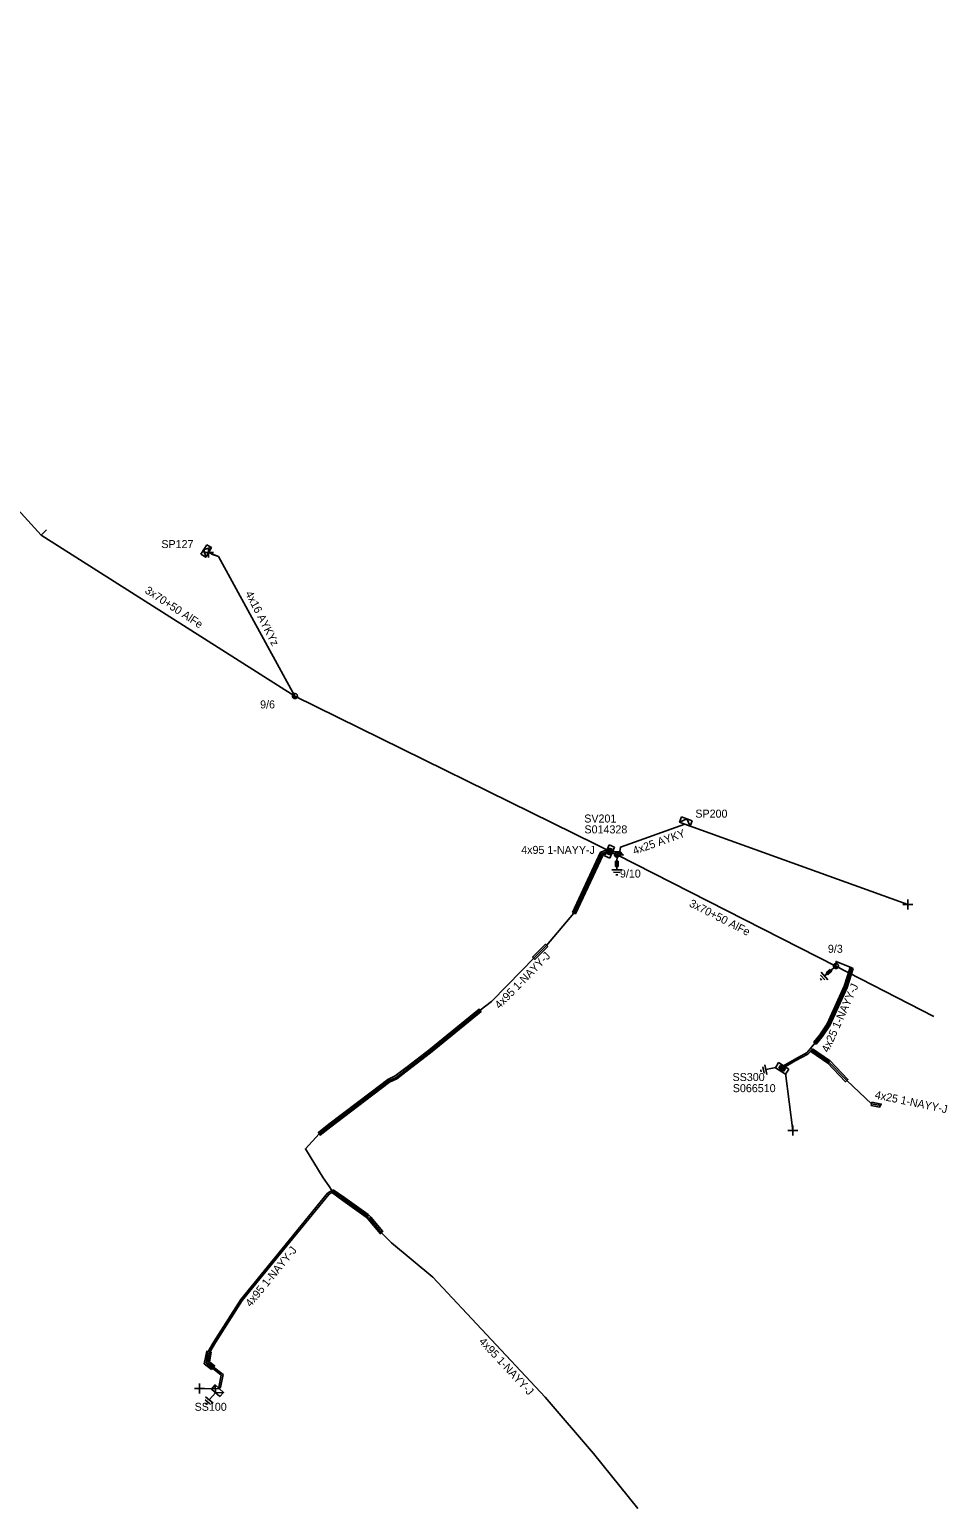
# Model space of a CAD drawing. Extents: x -717562 to -713845, y -1151196 to -1143903.
# Drawn here: x -714057.9 to -713943.2, y -1147276.3 to -1147091.5 of the extents above; entities that cross this region are included whole.
import ezdxf

# ---------------------------------------------------------------- set-up
doc = ezdxf.new("R2010")
doc.units = 0
for name, color, linetype in [('Vrstva 1', 7, 'Continuous'), ('Vrstva 12', 7, 'Continuous'), ('Vrstva 13', 7, 'Continuous'), ('Vrstva 14', 7, 'Continuous'), ('Vrstva 15', 7, 'Continuous'), ('Vrstva 16', 7, 'Continuous'), ('Vrstva 19', 7, 'Continuous'), ('Vrstva 2', 7, 'Continuous'), ('Vrstva 20', 7, 'Continuous'), ('Vrstva 28', 7, 'Continuous'), ('Vrstva 29', 7, 'Continuous'), ('Vrstva 30', 7, 'Continuous'), ('Vrstva 31', 7, 'Continuous'), ('Vrstva 33', 7, 'Continuous'), ('Vrstva 34', 7, 'Continuous'), ('Vrstva 4', 7, 'Continuous'), ('Vrstva 5', 7, 'Continuous'), ('Vrstva 52', 7, 'Continuous'), ('Vrstva 54', 7, 'Continuous'), ('Vrstva 55', 7, 'Continuous'), ('Vrstva 59', 7, 'Continuous'), ('Vrstva 6', 7, 'Continuous'), ('Vrstva 8', 7, 'Continuous'), ('Vrstva 9', 7, 'Continuous')]:
    doc.layers.add(name, color=color, linetype=linetype)

# ---------------------------------------------------------------- blocks, each defined once
blk = doc.blocks.new('NN440')
at = {"layer": 'Vrstva 2'}
for points in [[(0.63, 0), (0.63, 0.06), (0.62, 0.13), (0.6, 0.19), (0.58, 0.25), (0.55, 0.31), (0.51, 0.37), (0.47, 0.42), (0.42, 0.46), (0.37, 0.51), (0.32, 0.54), (0.26, 0.57), (0.2, 0.59), (0.13, 0.61), (0.07, 0.62), (0, 0.63), (-0.06, 0.62), (-0.13, 0.61), (-0.19, 0.59), (-0.26, 0.57), (-0.31, 0.54), (-0.37, 0.51), (-0.42, 0.46), (-0.47, 0.42), (-0.51, 0.37), (-0.54, 0.31), (-0.57, 0.25), (-0.6, 0.19), (-0.62, 0.13), (-0.63, 0.06), (-0.63, 0), (-0.63, -0.07), (-0.62, -0.14), (-0.6, -0.2), (-0.57, -0.26), (-0.54, -0.32), (-0.51, -0.37), (-0.47, -0.43), (-0.42, -0.47), (-0.37, -0.51), (-0.31, -0.55), (-0.26, -0.58), (-0.19, -0.6), (-0.13, -0.62), (-0.06, -0.63), (0, -0.63), (0.07, -0.63), (0.13, -0.62), (0.2, -0.6), (0.26, -0.58), (0.32, -0.55), (0.37, -0.51), (0.42, -0.47), (0.47, -0.43), (0.51, -0.37), (0.55, -0.32), (0.58, -0.26), (0.6, -0.2), (0.62, -0.14), (0.63, -0.07), (0.63, 0)], [(-0.63, 0), (0.63, 0)], [(-0.6, -0.18), (0.57, -0.18)], [(-0.51, -0.32), (0.5, -0.32)], [(-0.37, -0.47), (0.35, -0.47)]]:
    blk.add_lwpolyline(points, dxfattribs=at)
blk = doc.blocks.new('NN870')
at = {"layer": 'Vrstva 4'}
for points in [[(0, -0.25), (0.5, 0), (0, 0.25), (-0.5, 0), (0, -0.25)], [(0.37, 0), (0, 0.19), (-0.36, 0), (0, -0.19), (0.37, 0)], [(0.24, 0), (0, 0.12), (-0.25, 0), (0, -0.12), (0.24, 0)], [(0.12, 0), (0, 0.06), (-0.13, 0), (0, -0.06), (0.12, 0)]]:
    blk.add_lwpolyline(points, dxfattribs=at)
blk = doc.blocks.new('NN800')
at = {"layer": 'Vrstva 1'}
for points in [[(-0.44, 0.44), (0.44, -0.44)], [(-0.44, -0.44), (0.44, 0.44)]]:
    blk.add_lwpolyline(points, dxfattribs=at)
blk = doc.blocks.new('NN820')
at = {"layer": 'Vrstva 13'}
for points in [[(0, 0), (0, -1.05)], [(-0.16, -0.81), (0.16, -0.81)], [(-0.16, -1.47), (-0.16, -0.81)], [(0.16, -1.47), (-0.16, -1.47)], [(0, -1.05), (-0.06, -0.93)], [(0, -1.05), (0.06, -0.93)], [(0, -1.47), (0, -1.87)], [(0.16, -0.81), (0.16, -1.47)]]:
    blk.add_lwpolyline(points, dxfattribs=at)
blk = doc.blocks.new('NN620')
at = {"layer": 'Vrstva 8'}
for points in [[(0.75, 0), (-0.75, 0)], [(-0.75, 0), (-0.75, -0.75)], [(0.75, -0.75), (0.75, 0)], [(-0.75, -0.75), (0.75, -0.75)], [(0.37, -0.18), (-0.38, -0.18)], [(-0.38, -0.18), (-0.38, -0.56)], [(-0.38, -0.56), (0.37, -0.56)], [(0.32, -0.23), (-0.33, -0.23)], [(-0.33, -0.23), (-0.33, -0.51)], [(-0.33, -0.51), (0.32, -0.51)], [(0.27, -0.27), (-0.28, -0.27)], [(-0.28, -0.27), (-0.28, -0.46)], [(-0.28, -0.46), (0.27, -0.46)], [(0.23, -0.32), (-0.23, -0.32)], [(-0.23, -0.32), (-0.23, -0.42)], [(-0.23, -0.42), (0.23, -0.42)], [(-0.19, -0.37), (0.19, -0.37)], [(0.23, -0.42), (0.23, -0.32)], [(0.27, -0.46), (0.27, -0.27)], [(0.32, -0.51), (0.32, -0.23)], [(0.37, -0.56), (0.37, -0.18)]]:
    blk.add_lwpolyline(points, dxfattribs=at)
blk = doc.blocks.new('NN630')
at = {"layer": 'Vrstva 9'}
for points in [[(0, -0.7), (-0.7, 0)], [(-0.7, -0.7), (-0.7, 0), (0.7, 0), (0.7, -0.7)], [(-0.7, -0.7), (0.7, -0.7)], [(0, -0.7), (0.7, 0)]]:
    blk.add_lwpolyline(points, dxfattribs=at)
blk = doc.blocks.new('NN810')
at = {"layer": 'Vrstva 14'}
for points in [[(0, -0.64), (0, -1.89)], [(0.63, -1.89), (-0.62, -1.89)], [(0.39, -2.2), (-0.4, -2.2)], [(0, -2.52), (-0.12, -2.52)], [(0.14, -2.52), (0, -2.52)]]:
    blk.add_lwpolyline(points, dxfattribs=at)
blk = doc.blocks.new('NN510')
at = {"layer": 'Vrstva 2'}
blk.add_lwpolyline([(0, 0), (0, 0.94)], dxfattribs=at)

msp = doc.modelspace()

# ---------------------------------------------------------------- linework, layer by layer
at = {"layer": 'Vrstva 1'}
for points in [[(-713984.48, -1147194.64), (-714024.75, -1147174.82), (-714056.47, -1147154.69), (-714081.76, -1147126.93), (-714098.54, -1147091.52)], [(-713957.11, -1147208.56), (-713984.48, -1147194.64)], [(-713944.86, -1147214.88), (-713957.11, -1147208.56)]]:
    msp.add_lwpolyline(points, dxfattribs=at)
at = {"layer": 'Vrstva 20'}
for points in [[(-713990.05, -1147201.86), (-713986.53, -1147194.34), (-713985.84, -1147194.09), (-713985.7, -1147194.46), (-713986.23, -1147194.66), (-713989.69, -1147202.02)], [(-713993.15, -1147206.12), (-713994.75, -1147207.73), (-713995.03, -1147207.45), (-713993.43, -1147205.84)], [(-713954.95, -1147208.85), (-713955.7, -1147211.23), (-713957.86, -1147216), (-713958.82, -1147217.39), (-713959.14, -1147217.17), (-713958.2, -1147215.8), (-713956.08, -1147211.09), (-713955.33, -1147208.73)], [(-714001.46, -1147214.23), (-714007.78, -1147219.39), (-714010.49, -1147221.49), (-714012.01, -1147222.64), (-714012.92, -1147223.07), (-714014.99, -1147224.64), (-714020.27, -1147228.64), (-714021.58, -1147229.68), (-714021.82, -1147229.36), (-714020.51, -1147228.32), (-714015.23, -1147224.32), (-714013.12, -1147222.73), (-714012.21, -1147222.3), (-714010.73, -1147221.17), (-714008.02, -1147219.07), (-714001.72, -1147213.93)], [(-713958.83, -1147217.41), (-713959.59, -1147218.32), (-713959.89, -1147218.06), (-713959.13, -1147217.15)], [(-713960.04, -1147218.9), (-713957.92, -1147220.36), (-713958.14, -1147220.68), (-713960.26, -1147219.22)], [(-713957.89, -1147220.38), (-713955.62, -1147222.73), (-713955.9, -1147223.01), (-713958.17, -1147220.66)], [(-713952.62, -1147225.57), (-713951.45, -1147225.82), (-713951.66, -1147226.18), (-713952.7, -1147225.97)], [(-714019.95, -1147236.51), (-714018.53, -1147237.52), (-714015.59, -1147239.62), (-714015.83, -1147239.94), (-714018.77, -1147237.84), (-714020.19, -1147236.83)], [(-714015.57, -1147239.64), (-714015.28, -1147239.93), (-714013.77, -1147241.75), (-714014.07, -1147242.01), (-714015.58, -1147240.19), (-714015.85, -1147239.92)], [(-714035.18, -1147258.98), (-714036.08, -1147258.26), (-714035.78, -1147256.7), (-714035.2, -1147256.82), (-714035.42, -1147258.02), (-714034.8, -1147258.52)]]:
    msp.add_lwpolyline(points, close=True, dxfattribs=at)
at = {"layer": 'Vrstva 5'}
for points in [[(-713985.77, -1147194.27), (-713986.38, -1147194.5), (-713989.87, -1147201.94), (-713993.29, -1147205.98), (-713994.89, -1147207.59), (-713996.38, -1147209.12), (-714000.17, -1147213), (-714001.59, -1147214.08), (-714007.9, -1147219.23), (-714010.61, -1147221.33), (-714012.11, -1147222.47), (-714013.02, -1147222.9), (-714015.11, -1147224.48), (-714020.39, -1147228.48), (-714021.7, -1147229.52), (-714023.43, -1147231.39), (-714021.21, -1147235.03), (-714020.51, -1147236.04), (-714020.13, -1147236.59), (-714020.67, -1147236.94), (-714026.34, -1147243.9), (-714031.52, -1147250.23), (-714034.87, -1147255.51), (-714035.59, -1147256.72), (-714035.86, -1147258.18), (-714035.05, -1147258.83), (-714033.96, -1147259.7), (-714034.27, -1147261.2), (-714034.2, -1147261.38), (-714034.07, -1147261.25), (-714033.74, -1147259.62), (-714034.93, -1147258.67), (-714035.64, -1147258.1), (-714035.39, -1147256.8), (-714034.69, -1147255.61), (-714031.36, -1147250.35), (-714026.18, -1147244.02), (-714020.53, -1147237.1), (-714019.98, -1147236.73), (-714019.42, -1147237.13), (-714018.65, -1147237.68), (-714015.71, -1147239.78), (-714015.43, -1147240.06), (-714013.92, -1147241.88), (-714012.66, -1147243.14), (-714007.52, -1147247.45), (-714000.78, -1147254.59), (-713993.48, -1147262.44), (-713987.42, -1147269.49), (-713981.87, -1147276.34)], [(-713984.48, -1147194.64), (-713985.08, -1147194.39)], [(-713957.11, -1147208.56), (-713957.1, -1147207.98), (-713955.14, -1147208.79), (-713955.89, -1147211.16), (-713958.03, -1147215.9), (-713958.98, -1147217.28), (-713959.74, -1147218.19), (-713960.72, -1147219.38), (-713962.3, -1147220.22), (-713963.65, -1147221.03)], [(-713963.55, -1147221.2), (-713962.2, -1147220.39), (-713960.63, -1147219.56), (-713960.15, -1147219.06), (-713958.03, -1147220.52), (-713955.76, -1147222.87), (-713952.66, -1147225.77), (-713951.55, -1147226)]]:
    msp.add_lwpolyline(points, dxfattribs=at)
at = {"layer": 'Vrstva 52'}
for points in [[(-713984.16, -1147194.48), (-713984.05, -1147193.69), (-713976.01, -1147190.82)], [(-713985, -1147194.2), (-713984.65, -1147194.29), (-713984.16, -1147194.48)]]:
    msp.add_lwpolyline(points, dxfattribs=at)
at = {"layer": 'Vrstva 54'}
msp.add_lwpolyline([(-714024.75, -1147174.82), (-714034.31, -1147157.39), (-714035.55, -1147156.86)], dxfattribs=at)
at = {"layer": 'Vrstva 59'}
for points in [[(-713976.01, -1147190.82), (-713948.13, -1147200.88)], [(-713963.44, -1147221.95), (-713962.5, -1147229.11)], [(-714034.2, -1147261.38), (-714036.69, -1147261.37)]]:
    msp.add_lwpolyline(points, dxfattribs=at)

# ---------------------------------------------------------------- block references
at = {"layer": 'Vrstva 13'}
for p, rotation in [((-714056.47, -1147154.69), -46.27303056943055), ((-714034.31, -1147157.39), 69.69826659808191)]:
    msp.add_blockref('NN510', p, dxfattribs=dict(at, rotation=rotation))
for p, xscale, yscale, rotation in [((-714024.75, -1147174.82), 0.5000000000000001, 0.5, -32.831219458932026), ((-713984.49, -1147194.63), 0.5, 0.5, -26.301177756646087), ((-713957.11, -1147208.56), 0.5, 0.49999999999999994, -27.029194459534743)]:
    msp.add_blockref('NN440', p, dxfattribs=dict(at, xscale=xscale, yscale=yscale, rotation=rotation))
at = {"layer": 'Vrstva 15'}
for p, rotation in [((-713984.48, -1147194.64), -1.0613190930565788), ((-713957.11, -1147208.56), -48.99300825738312), ((-713964.02, -1147221.11), -78.17452250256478), ((-714034.2, -1147261.38), -41.75156236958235)]:
    msp.add_blockref('NN810', p, dxfattribs=dict(at, rotation=rotation))
at = {"layer": 'Vrstva 16'}
for p, rotation in [((-713984.48, -1147194.64), -1.0613190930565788), ((-713957.11, -1147208.56), -48.99300825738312)]:
    msp.add_blockref('NN820', p, dxfattribs=dict(at, rotation=rotation))
at = {"layer": 'Vrstva 19', "rotation": 158.80594348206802}
msp.add_blockref('NN870', (-713984.16, -1147194.48), dxfattribs=at)
at = {"layer": 'Vrstva 28'}
for p, rotation in [((-713985.08, -1147194.39), -113.02727314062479), ((-713963.65, -1147221.03), -32.0053831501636)]:
    msp.add_blockref('NN620', p, dxfattribs=dict(at, rotation=rotation))
at = {"layer": 'Vrstva 31'}
for p, rotation in [((-714035.54, -1147156.86), -120.91692220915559), ((-713976.01, -1147190.82), 158.55857786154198), ((-714034.2, -1147261.38), -41.75156236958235)]:
    msp.add_blockref('NN630', p, dxfattribs=dict(at, rotation=rotation))
at = {"layer": 'Vrstva 34'}
for p, rotation in [((-714035.54, -1147156.86), 45), ((-713948.13, -1147200.88), 45), ((-713962.5, -1147229.11), 45), ((-714036.69, -1147261.37), 45.00000009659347)]:
    msp.add_blockref('NN800', p, dxfattribs=dict(at, rotation=rotation))

# ---------------------------------------------------------------- texts
at = {"layer": 'Vrstva 12'}
for s, p in [('9/6', (-714029.1, -1147176.36)), ('9/10', (-713984.12, -1147197.5)), ('9/3', (-713958.12, -1147206.9))]:
    msp.add_text(s, height=1, dxfattribs=at).set_placement(p)
at = {"layer": 'Vrstva 2'}
for rotation, p in [(326.671, (-714043.6, -1147161.85)), (332.97, (-713975.55, -1147201.05))]:
    msp.add_text('3x70+50 AlFe', height=1, rotation=rotation, dxfattribs=at).set_placement(p)
at = {"layer": 'Vrstva 29'}
for s, p in [('S014328', (-713988.55, -1147191.98)), ('S066510', (-713970.01, -1147224.32))]:
    msp.add_text(s, height=1, dxfattribs=at).set_placement(p)
at = {"layer": 'Vrstva 30'}
for s, p in [('SV201', (-713988.58, -1147190.62)), ('SS300', (-713970.04, -1147222.93))]:
    msp.add_text(s, height=1, dxfattribs=at).set_placement(p)
at = {"layer": 'Vrstva 33'}
for s, p in [('SP127', (-714041.45, -1147156.32)), ('SP200', (-713974.69, -1147190.01)), ('SS100', (-714037.29, -1147264.14))]:
    msp.add_text(s, height=1, dxfattribs=at).set_placement(p)
at = {"layer": 'Vrstva 54'}
msp.add_text('4x25 AYKY', height=1, rotation=19.653, dxfattribs=at).set_placement((-713982.31, -1147194.66))
at = {"layer": 'Vrstva 55'}
msp.add_text('4x16 AYKYz', height=1, rotation=297.063, dxfattribs=at).set_placement((-714030.98, -1147161.99))
at = {"layer": 'Vrstva 6'}
msp.add_text('4x95 1-NAYY-J', height=1, dxfattribs=at).set_placement((-713996.46, -1147194.54))
for s, rotation, p in [('4x95 1-NAYY-J', 45.672, (-713999.17, -1147213.98)), ('4x25 1-NAYY-J', 65.702, (-713958.06, -1147219.43)), ('4x25 1-NAYY-J', 348.257, (-713952.31, -1147225.09)), ('4x95 1-NAYY-J', 50.706, (-714030.28, -1147251.24)), ('4x95 1-NAYY-J', 312.921, (-714001.81, -1147255.54))]:
    msp.add_text(s, height=1, rotation=rotation, dxfattribs=at).set_placement(p)

doc.saveas('drawing.dxf')
